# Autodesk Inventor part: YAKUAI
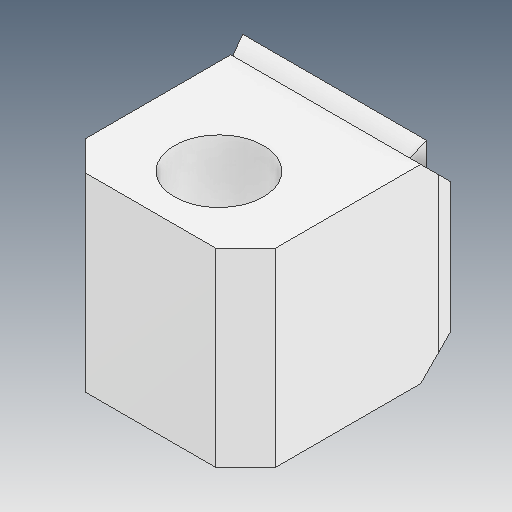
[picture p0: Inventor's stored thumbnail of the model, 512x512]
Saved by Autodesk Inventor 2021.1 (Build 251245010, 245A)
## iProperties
Created: 2021-05
Part Number: YAKUAI
Material: Ogólny
Document SubType Name: Modeling
Designer: user
Density: 1 g/cm^3
Appearance: Domyślna
Author: user
Revision Number: ÈÎºÎ
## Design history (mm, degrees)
feature "ÊäÈë1"
feature "ÊäÈë2"
feature "ÊäÈë3"
node "Bryła1"
node "Bryła2"
node "Bryła3"
